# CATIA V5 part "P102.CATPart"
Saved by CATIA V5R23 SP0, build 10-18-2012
Part number: P102
Definition: Pignon 12 dents
Description: Pignon  12 dents A Chaine Menant
Bounding box of the stored display mesh (mm): x -12 to 5, y -29.854 to 29.854, z -29.854 to 29.854
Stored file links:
  C:\wamp\www\COURS\CONCEPTION GMP1\TITRE 02-SEMESTRE 2\03-TP7-PRESSE MECANIQUE\eleve\P102.CATPart
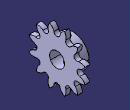
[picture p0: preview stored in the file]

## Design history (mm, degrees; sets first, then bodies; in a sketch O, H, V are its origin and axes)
Body1 (main body)
  Sketch1 on yz-plane, origin (0, 0, 0), H (0, 1, 0), V (0, 0, 1)
    construction circle A1 centre (0, 0) radius 24.5345
    construction line L1 (0, 0) -> (0, 34.5291)
    construction line L2 (0, 0) -> (-17.2645, 29.9031)
    construction line L3 (0.4087, -0.2231) -> (-29.502, 17.0281)
    construction line L4 (0.4655, 0.0111) -> (-34.0636, -0.0042)
    construction line L5 (0.3976, 0.2423) -> (-29.4978, -17.0355)
    construction line L6 (-33.8588, -8.8396) -> (-3.921, -26.0438)
    construction line L7 (-0.0111, 0.4655) -> (0.0042, -34.0636)
    construction line L8 (-0.2423, 0.3976) -> (17.0355, -29.4978)
    construction line L9 (-0.4087, 0.2231) -> (29.502, -17.0281)
    construction line L10 (-0.4655, -0.0111) -> (34.0636, 0.0042)
    construction line L11 (-0.3976, -0.2423) -> (29.4978, 17.0355)
    construction line L12 (0, 0) -> (17.2645, 29.9031)
    construction line L13 (0, 0) -> (0, 34.5291)
    arc A2 centre (0, 24.5345) radius 3.175 from (-3.1683, 24.3291) to (3.1683, 24.3291) ccw
    point P26 (0, 24.5345)
    arc A3 centre (-12.2673, 21.2475) radius 3.175 from (-14.9084, 19.4854) to (-9.4207, 22.6538) ccw
    point P27 (-12.2673, 21.2475)
    arc A4 centre (-21.2475, 12.2673) radius 3.175 from (-22.6538, 9.4207) to (-19.4854, 14.9084) ccw
    point P28 (-21.2475, 12.2673)
    arc A5 centre (-24.5345, 0) radius 3.175 from (-24.3291, -3.1683) to (-24.3291, 3.1683) ccw
    point P29 (-24.5345, 0)
    arc A6 centre (-21.2475, -12.2673) radius 3.175 from (-19.4854, -14.9084) to (-22.6538, -9.4207) ccw
    point P30 (-21.2475, -12.2673)
    arc A7 centre (-12.2673, -21.2475) radius 3.175 from (-9.0989, -21.453) to (-14.9084, -19.4854) ccw
    point P31 (-12.2673, -21.2475)
    arc A8 centre (0, -24.5345) radius 3.175 from (3.1683, -24.3291) to (-3.1683, -24.3291) ccw
    point P32 (0, -24.5345)
    arc A9 centre (12.2673, -21.2475) radius 3.175 from (14.9084, -19.4854) to (9.4207, -22.6538) ccw
    point P33 (12.2673, -21.2475)
    arc A10 centre (21.2475, -12.2673) radius 3.175 from (22.6538, -9.4207) to (19.4854, -14.9084) ccw
    point P34 (21.2475, -12.2673)
    arc A11 centre (24.5345, 0) radius 3.175 from (24.3291, 3.1683) to (24.3291, -3.1683) ccw
    point P35 (24.5345, 0)
    arc A12 centre (21.2475, 12.2673) radius 3.175 from (19.4854, 14.9084) to (22.6538, 9.4207) ccw
    point P36 (21.2475, 12.2673)
    arc A13 centre (12.2673, 21.2475) radius 3.175 from (9.4207, 22.6538) to (14.9084, 19.4854) ccw
    point P37 (12.2673, 21.2475)
    point P38 (-3.1683, 24.3291)
    arc A14 centre (0, 24.5345) radius 9.6066 from (9.4207, 22.6538) to (7.9993, 29.854) ccw
    point P39 (-9.4207, 22.6538)
    arc A15 centre (12.2673, 21.2475) radius 9.6066 from (19.4854, 14.9084) to (21.8546, 21.8546) ccw
    point P41 (3.1683, 24.3291)
    arc A16 centre (21.2475, 12.2673) radius 9.6066 from (24.3291, 3.1683) to (29.854, 7.9993) ccw
    point P43 (14.9084, 19.4854)
    point P44 (24.3291, 3.1683)
    arc A17 centre (24.5345, 0) radius 9.6066 from (22.6538, -9.4207) to (29.854, -7.9993) ccw
    point P45 (22.6538, 9.4207)
    point P46 (22.6538, -9.4207)
    arc A18 centre (21.2475, -12.2673) radius 9.6066 from (14.9084, -19.4854) to (21.8546, -21.8546) ccw
    point P47 (24.3291, -3.1683)
    point P48 (14.9084, -19.4854)
    arc A19 centre (12.2673, -21.2475) radius 9.6066 from (3.1683, -24.3291) to (7.9993, -29.854) ccw
    point P49 (19.4854, -14.9084)
    point P50 (3.1683, -24.3291)
    arc A20 centre (0, -24.5345) radius 9.6066 from (-9.0989, -21.453) to (-7.9993, -29.854) ccw
    point P51 (9.4207, -22.6538)
    arc A21 centre (-12.2673, -21.2475) radius 9.6066 from (-19.4854, -14.9084) to (-21.8546, -21.8546) ccw
    point P53 (-12.2673, -21.2475)
    point P54 (-3.1683, -24.3291)
    point P55 (-19.4854, -14.9084)
    arc A22 centre (-21.2475, -12.2673) radius 9.6066 from (-24.3291, -3.1683) to (-29.854, -7.9993) ccw
    point P56 (-14.9084, -19.4854)
    point P57 (-24.3291, -3.1683)
    arc A23 centre (-24.5345, 0) radius 9.6066 from (-22.6538, 9.4207) to (-29.854, 7.9993) ccw
    point P58 (-22.6538, -9.4207)
    point P59 (-22.6538, 9.4207)
    arc A24 centre (-21.2475, 12.2673) radius 9.6066 from (-14.9084, 19.4854) to (-21.8546, 21.8546) ccw
    point P60 (-24.3291, 3.1683)
    arc A25 centre (-12.2673, 21.2475) radius 9.6066 from (-3.1683, 24.3291) to (-7.9993, 29.854) ccw
    point P62 (-19.4854, 14.9084)
    point P63 (7.9993, 29.854)
    arc A26 centre (0, 24.5345) radius 9.6066 from (-7.9993, 29.854) to (-9.4207, 22.6538) ccw
    arc A27 centre (-12.2673, 21.2475) radius 9.6066 from (-21.8546, 21.8546) to (-19.4854, 14.9084) ccw
    arc A28 centre (-21.2475, 12.2673) radius 9.6066 from (-29.854, 7.9993) to (-24.3291, 3.1683) ccw
    arc A29 centre (-24.5345, 0) radius 9.6066 from (-29.854, -7.9993) to (-22.6538, -9.4207) ccw
    arc A30 centre (-21.2475, -12.2673) radius 9.6066 from (-21.8546, -21.8546) to (-14.9084, -19.4854) ccw
    arc A31 centre (-12.2673, -21.2475) radius 9.6066 from (-7.9993, -29.854) to (-3.1683, -24.3291) ccw
    point P70 (7.9993, -29.854)
    arc A32 centre (12.2673, -21.2475) radius 9.6066 from (21.8546, -21.8546) to (19.4854, -14.9084) ccw
    arc A33 centre (0, -24.5345) radius 9.6066 from (7.9993, -29.854) to (9.4207, -22.6538) ccw
    arc A34 centre (21.2475, -12.2673) radius 9.6066 from (29.854, -7.9993) to (24.3291, -3.1683) ccw
    arc A35 centre (24.5345, 0) radius 9.6066 from (29.854, 7.9993) to (22.6538, 9.4207) ccw
    arc A36 centre (21.2475, 12.2673) radius 9.6066 from (21.8546, 21.8546) to (14.9084, 19.4854) ccw
    arc A37 centre (12.2673, 21.2475) radius 9.6066 from (7.9993, 29.854) to (3.1683, 24.3291) ccw
    point P75 (22.6538, 9.4207)
    point P76 (24.3291, 3.1683)
    point P77 (24.3291, -3.1683)
    point P78 (22.6538, -9.4207)
    point P79 (19.4854, -14.9084)
    point P80 (14.9084, -19.4854)
    point P81 (3.1683, -24.3291)
    point P82 (-3.1683, -24.3291)
    point P83 (-14.9084, -19.4854)
    point P84 (-19.4854, -14.9084)
    point P85 (-22.6538, -9.4207)
    point P86 (-24.3291, -3.1683)
    point P87 (-24.3291, 3.1683)
    point P88 (-19.4854, 14.9084)
    point P89 (-3.1683, 24.3291)
    radius A2 = 3.175
    radius A3 = 3.175
    angle L2 L13 = 30
    radius A13 = 3.175
    radius A12 = 3.175
    radius A11 = 3.175
    radius A10 = 3.175
    radius A4 = 3.175
    radius A5 = 3.175
    radius A6 = 3.175
    radius A7 = 3.175
    radius A8 = 3.175
    radius A9 = 3.175
    distance P37 P36 = 12.7
    distance P36 P35 = 12.7
    distance P35 P34 = 12.7
    distance P34 P33 = 12.7
    distance P37 P26 = 12.7
    distance P26 P27 = 12.7
    distance P27 P28 = 12.7
    distance P28 P29 = 12.7
    distance P53 P30 = 12.7
    distance P32 P33 = 12.7
    distance P30 P29 = 12.7 (reference)
    distance P32 P53 = 12.7 (reference)
    radius A1 = 24.5345 (reference)
    vertical: L1 V
    coincidence: P26 L1, P26 A1, A1 P27, P28 L3, P28 A1, P29 L4, P29 A1, P30 L5, P30 A1, P31 L6, P31 A1, P32 L7, P32 A1, P33 L8, P33 A1, P34 L9, P34 A1, P35 L10, P35 A1, P36 L11, P36 A1, P37 A1, P38 A1, P39 A1, P41 A1, P43 A1, P44 A1, P45 A12, P45 A1, P46 A10, P47 A11, P47 A1, P48 A9, P49 A10, P49 A1, P50 A8, P51 A1, P53 L6, P53 A1, P54 A8, P54 A1, P55 A1, P56 A7, P56 A1, P57 A5, P58 A6, P58 A1, P60 A5, P60 A1, P62 A4, P62 A1, A15 P63, A14 A26, A25 A27, A24 A28, A23 A29, A22 A30, A21 A31, A20 P70, A19 A32, A20 A33, A18 A34, A17 A35, A16 A36, A15 A37, A1 P75, A1 P76, A1 P77, A1 P78, A1 P79, A1 P80, A1 P81, A1 P82, A1 P83, A1 P84, A1 P85, A1 P86, A1 P87, A1 P88, A1 P89, P54 P82, P55 P84, P58 P85, P60 P87, P62 P88, P57 P86, P59 A1
  Pad1: profile Sketch1, direction (1, 0, 0), length 5
  Sketch2 on face of Pad1, origin (0, 0, 0), H (0, -1, 0), V (0, 0, 1)
    circle A1 centre (0, 0) radius 17
    radius A1 = 17
  Pad2: profile Sketch2, direction (-1, 0, 0), length 12
  Sketch3 on xy-plane, origin (0, 0, 0), H (1, 0, 0), V (0, 1, 0)
    circle A1 centre (-6, 0) radius 3
    point P1 (-6, 0)
    reference projected line E1 (-12, 17) -> (-12, -17) from edge [face of Pad2 | face of Pad2]
    radius A1 = 3
    distance P1 E1 = 6
    coincidence: P1 H
  Pocket1: profile Sketch3, direction (0, 0, -1), length 21, mirrored extent
  Sketch4 on face of Pad2, origin (-12, 0, 0), H (0, 1, 0), V (0, 0, -1)
    point P1 (0, 0)
    reference projected circle E1 centre (0, 0) radius 17 from edge [face of Pad2 | face of Pad2]
    concentricity: P1 E1
  Hole1: placed by Sketch4, at (-12, 0, 0) direction (1, 0, 0), diameter 16, through (limit type 6)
